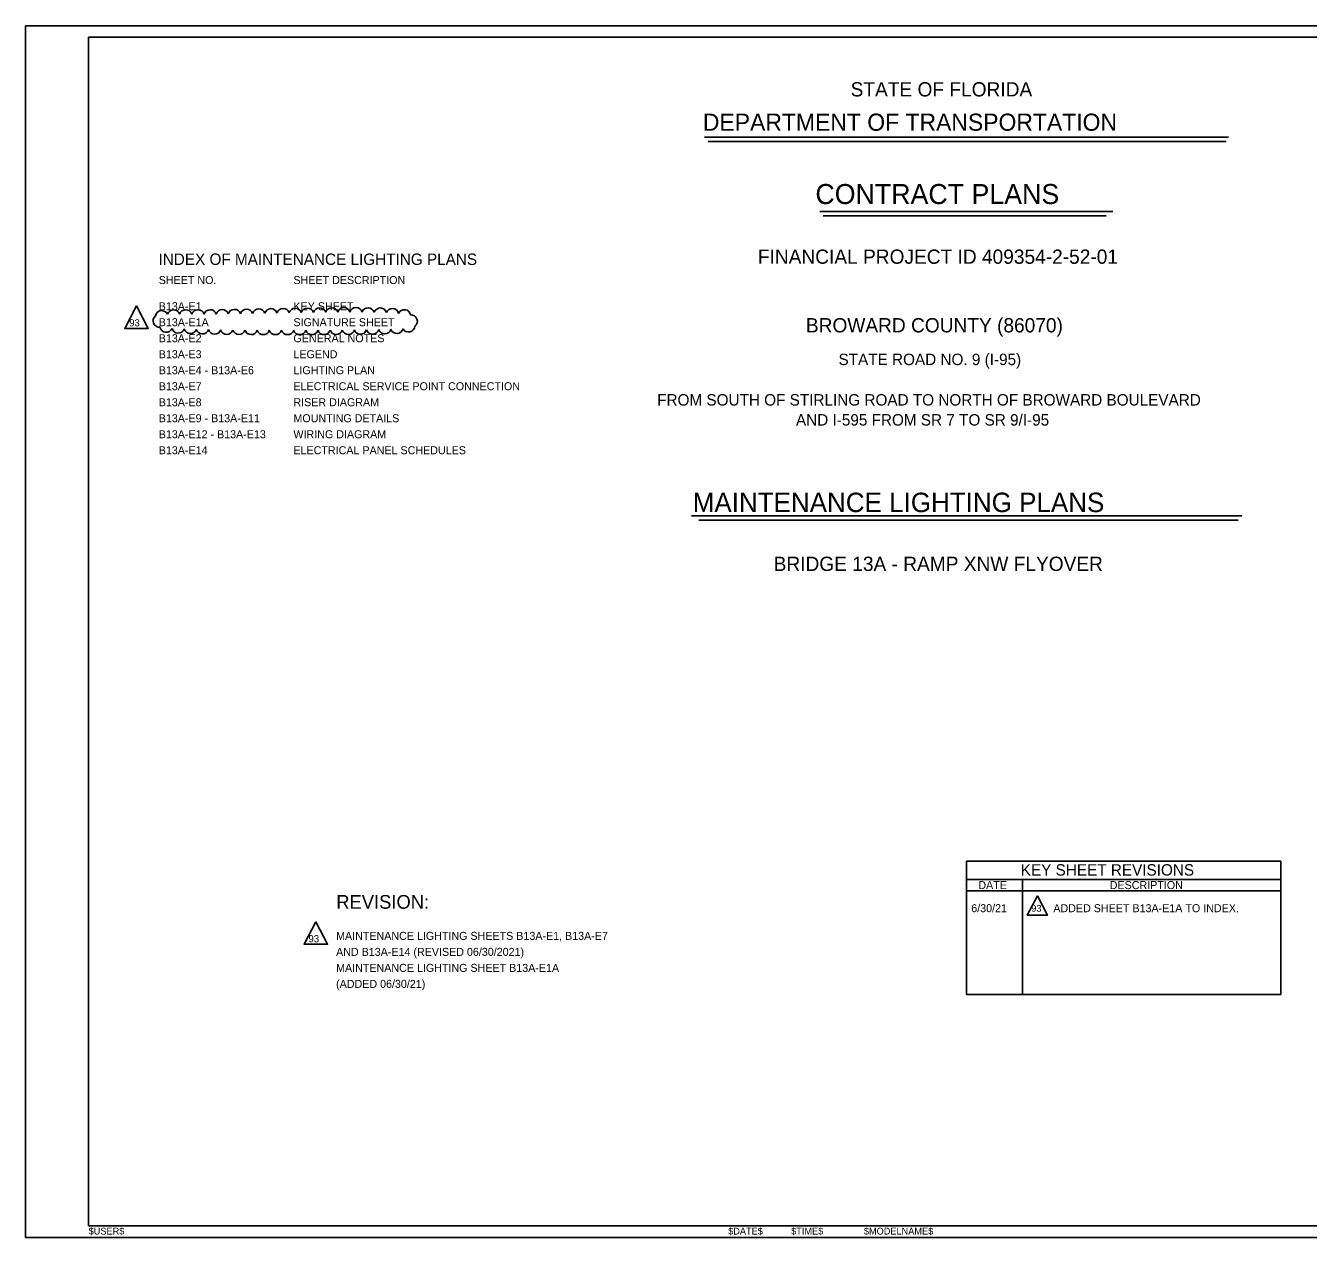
# Model space of a CAD drawing. Extents: x -828 to -798, y -2199 to -1895.
# Drawn here: x -820.23 to -809.01, y -2199.12 to -2188.52 of the extents above; entities that cross this region are included whole.
import ezdxf

# ---------------------------------------------------------------- set-up
doc = ezdxf.new("R2010")
doc.units = 0
for name, color, linetype in [('AdhocPoint_dp', 7, 'Continuous'), ('Cloud_dp', 7, 'Continuous'), ('PlotBorder_dp', 7, 'Continuous'), ('SheetBorder_dp', 7, 'Continuous'), ('SumBoxLines_dp', 7, 'Continuous'), ('TextLabel', 7, 'Continuous'), ('TextMinor', 7, 'Continuous'), ('TextNotes', 7, 'Continuous'), ('TextTitle', 7, 'Continuous')]:
    doc.layers.add(name, color=color, linetype=linetype)

msp = doc.modelspace()

# ---------------------------------------------------------------- linework, layer by layer
at = {"layer": 'AdhocPoint_dp'}
msp.add_line((-820.227, -2199.124), (-820.227, -2199.124), dxfattribs=at)
at = {"layer": 'Cloud_dp'}
msp.add_lwpolyline([(-811.379, -2196.135), (-811.467, -2196.305), (-811.291, -2196.305)], close=True, dxfattribs=at)
for centre, radius, start, end in [((-819.057, -2191.106), 0.0557, 129.0549, 274.0549), ((-819.037, -2191.072), 0.0558, 24.9461, 169.9461), ((-818.933, -2191.065), 0.0558, 18.189, 163.189), ((-818.827, -2191.064), 0.0558, 17.5, 162.5), ((-818.72, -2191.064), 0.0558, 17.5, 162.5), ((-818.614, -2191.064), 0.0558, 17.9882, 162.9882), ((-818.507, -2191.063), 0.0558, 18.4964, 163.4964), ((-818.401, -2191.061), 0.0558, 18.4964, 163.4964), ((-818.295, -2191.059), 0.0558, 18.4964, 163.4964), ((-818.188, -2191.057), 0.0558, 18.4964, 163.4964), ((-818.082, -2191.055), 0.0558, 18.4964, 163.4964), ((-817.975, -2191.053), 0.0558, 18.4964, 163.4964), ((-817.869, -2191.051), 0.0558, 18.4964, 163.4964), ((-817.763, -2191.05), 0.0558, 18.4958, 163.4958), ((-817.656, -2191.048), 0.0558, 18.3592, 163.3592), ((-817.55, -2191.047), 0.0558, 18.0818, 163.0818), ((-817.444, -2191.046), 0.0558, 17.7357, 162.7357), ((-817.338, -2191.046), 0.0558, 17.2865, 162.2865), ((-817.232, -2191.047), 0.0558, 16.6703, 161.6703), ((-817.125, -2191.049), 0.0558, 15.748, 160.748), ((-817.02, -2191.054), 0.0558, 14.1312, 159.1312), ((-816.915, -2191.064), 0.0558, 9.8484, 154.8484), ((-816.857, -2191.11), 0.0557, 308.5193, 93.5193), ((-818.998, -2191.15), 0.0558, 192.0583, 337.0583), ((-818.893, -2191.158), 0.0558, 194.6421, 339.6421), ((-818.787, -2191.162), 0.0558, 195.6052, 340.6052), ((-818.681, -2191.165), 0.0558, 196.1537, 341.1537), ((-818.574, -2191.167), 0.0558, 196.52, 341.52), ((-818.468, -2191.169), 0.0558, 196.7871, 341.7871), ((-818.362, -2191.17), 0.0558, 196.9929, 341.9929), ((-818.255, -2191.171), 0.0558, 197.1578, 342.1578), ((-818.149, -2191.171), 0.0558, 197.2939, 342.2939), ((-818.043, -2191.171), 0.0558, 197.4086, 342.4086), ((-817.936, -2191.171), 0.0558, 197.5029, 342.5029), ((-817.83, -2191.171), 0.0558, 197.5761, 342.5761), ((-817.724, -2191.171), 0.0558, 197.6587, 342.6587), ((-817.617, -2191.171), 0.0558, 197.7574, 342.7574), ((-817.511, -2191.17), 0.0558, 197.8782, 342.8782), ((-817.405, -2191.169), 0.0558, 198.031, 343.031), ((-817.299, -2191.168), 0.0558, 198.2328, 343.2328), ((-817.192, -2191.167), 0.0558, 198.5173, 343.5173), ((-817.086, -2191.164), 0.0558, 198.9638, 343.9638), ((-816.98, -2191.161), 0.0558, 199.8314, 344.8314), ((-816.878, -2191.148), 0.0557, 209.2454, 354.2454)]:
    msp.add_arc(centre, radius, start, end, dxfattribs=at)
at = {"layer": 'PlotBorder_dp'}
msp.add_lwpolyline([(-820.227, -2199.124), (-803.727, -2199.124), (-803.727, -2188.524), (-820.227, -2188.524)], close=True, dxfattribs=at)
at = {"layer": 'SheetBorder_dp'}
for p, q in [((-819.677, -2188.624), (-819.677, -2199.024)), ((-819.677, -2188.624), (-804.277, -2188.624)), ((-819.677, -2199.024), (-804.277, -2199.024))]:
    msp.add_line(p, q, dxfattribs=at)
at = {"layer": 'SumBoxLines_dp'}
for p, q in [((-811.999, -2195.832), (-811.999, -2197)), ((-811.999, -2195.832), (-809.251, -2195.832)), ((-809.251, -2195.832), (-809.251, -2197)), ((-811.999, -2195.992), (-809.251, -2195.992)), ((-811.509, -2195.992), (-811.509, -2197)), ((-811.999, -2196.092), (-809.251, -2196.092)), ((-811.999, -2197), (-809.251, -2197))]:
    msp.add_line(p, q, dxfattribs=at)
at = {"layer": 'TextNotes'}
for points in [[(-819.257, -2190.974), (-819.36, -2191.172), (-819.155, -2191.172)], [(-817.69, -2196.363), (-817.792, -2196.56), (-817.587, -2196.56)]]:
    msp.add_lwpolyline(points, close=True, dxfattribs=at)
at = {"layer": 'TextTitle'}
for p, q in [((-814.289, -2189.5), (-809.707, -2189.5)), ((-814.257, -2189.538), (-809.729, -2189.538)), ((-813.281, -2190.15), (-810.719, -2190.15)), ((-813.253, -2190.188), (-810.777, -2190.188)), ((-814.404, -2192.813), (-809.59, -2192.813)), ((-814.339, -2192.851), (-809.624, -2192.851))]:
    msp.add_line(p, q, dxfattribs=at)

# ---------------------------------------------------------------- texts
at = {"layer": 'Cloud_dp'}
msp.add_text('93', height=0.06, rotation=0, dxfattribs=at).set_placement((-811.432, -2196.275))
at = {"layer": 'TextLabel'}
for s, height, p in [('INDEX OF MAINTENANCE LIGHTING PLANS', 0.1, (-819.065, -2190.617)), ('FINANCIAL PROJECT ID 409354-2-52-01', 0.125, (-813.823, -2190.607)), ('B13A-E1', 0.07, (-819.063, -2191.013)), ('KEY SHEET', 0.07, (-817.885, -2191.013)), ('B13A-E1A', 0.07, (-819.063, -2191.153)), ('SIGNATURE SHEET', 0.07, (-817.885, -2191.153)), ('BROWARD COUNTY (86070)', 0.125, (-813.403, -2191.207)), ('B13A-E2', 0.07, (-819.063, -2191.293)), ('GENERAL NOTES', 0.07, (-817.885, -2191.293)), ('B13A-E3', 0.07, (-819.063, -2191.433)), ('LEGEND', 0.07, (-817.885, -2191.433)), ('STATE ROAD NO. 9 (I-95)', 0.1, (-813.118, -2191.493)), ('B13A-E4 - B13A-E6', 0.07, (-819.063, -2191.573)), ('LIGHTING PLAN', 0.07, (-817.885, -2191.573)), ('B13A-E7', 0.07, (-819.063, -2191.713)), ('ELECTRICAL SERVICE POINT CONNECTION', 0.07, (-817.885, -2191.713)), ('FROM SOUTH OF STIRLING ROAD TO NORTH OF BROWARD BOULEVARD', 0.1, (-814.704, -2191.847)), ('B13A-E8', 0.07, (-819.063, -2191.853)), ('RISER DIAGRAM', 0.07, (-817.885, -2191.853)), ('B13A-E9 - B13A-E11', 0.07, (-819.063, -2191.993)), ('MOUNTING DETAILS', 0.07, (-817.885, -2191.993)), ('AND I-595 FROM SR 7 TO SR 9/I-95', 0.1, (-813.49, -2192.022)), ('B13A-E12 - B13A-E13', 0.07, (-819.063, -2192.133)), ('WIRING DIAGRAM', 0.07, (-817.885, -2192.133)), ('B13A-E14', 0.07, (-819.063, -2192.273)), ('ELECTRICAL PANEL SCHEDULES', 0.07, (-817.885, -2192.273)), ('BRIDGE 13A - RAMP XNW FLYOVER', 0.125, (-813.685, -2193.294)), ('KEY SHEET REVISIONS', 0.1, (-811.524, -2195.959)), ('REVISION:', 0.12, (-817.51, -2196.249))]:
    msp.add_text(s, height=height, dxfattribs=at).set_placement(p)
at = {"layer": 'TextMinor'}
for s, p in [('6/30/21', (-811.957, -2196.279)), ('ADDED SHEET B13A-E1A TO INDEX.', (-811.239, -2196.279))]:
    msp.add_text(s, height=0.07, dxfattribs=at).set_placement(p)
for s, p in [('$USER$', (-819.676, -2199.099)), ('$DATE$', (-814.083, -2199.099)), ('$TIME$', (-813.532, -2199.099)), ('$MODELNAME$', (-812.896, -2199.099))]:
    msp.add_text(s, height=0.06, rotation=360, dxfattribs=at).set_placement(p)
at = {"layer": 'TextNotes'}
for s, p in [('SHEET NO.', (-819.063, -2190.784)), ('SHEET DESCRIPTION', (-817.885, -2190.784)), ('DATE', (-811.895, -2196.077)), ('DESCRIPTION', (-810.746, -2196.077)), ('MAINTENANCE LIGHTING SHEETS B13A-E1, B13A-E7 ', (-817.512, -2196.521)), ('AND B13A-E14 (REVISED 06/30/2021)', (-817.512, -2196.661)), ('MAINTENANCE LIGHTING SHEET B13A-E1A ', (-817.512, -2196.801)), ('(ADDED 06/30/21)', (-817.512, -2196.941))]:
    msp.add_text(s, height=0.07, dxfattribs=at).set_placement(p)
for p in [(-819.321, -2191.154), (-817.753, -2196.542)]:
    msp.add_text('93', height=0.0622, rotation=0, dxfattribs=at).set_placement(p)
at = {"layer": 'TextTitle'}
for s, height, p in [('STATE OF FLORIDA', 0.125, (-813.012, -2189.143)), ('DEPARTMENT OF TRANSPORTATION', 0.15, (-814.304, -2189.443)), ('CONTRACT PLANS', 0.175, (-813.32, -2190.084)), ('MAINTENANCE LIGHTING PLANS', 0.17, (-814.393, -2192.779))]:
    msp.add_text(s, height=height, dxfattribs=at).set_placement(p)

doc.saveas('drawing.dxf')
